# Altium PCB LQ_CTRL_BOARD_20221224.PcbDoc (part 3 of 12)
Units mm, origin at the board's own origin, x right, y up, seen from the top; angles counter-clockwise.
Board outline 260 x 142 mm, 6 copper layers (Top Layer, Mid-Layer 1, Mid-Layer 2, Mid-Layer 3, Mid-Layer 4, Bottom Layer); 1105 components, 1039 nets, 3898 pads, 1277 vias.
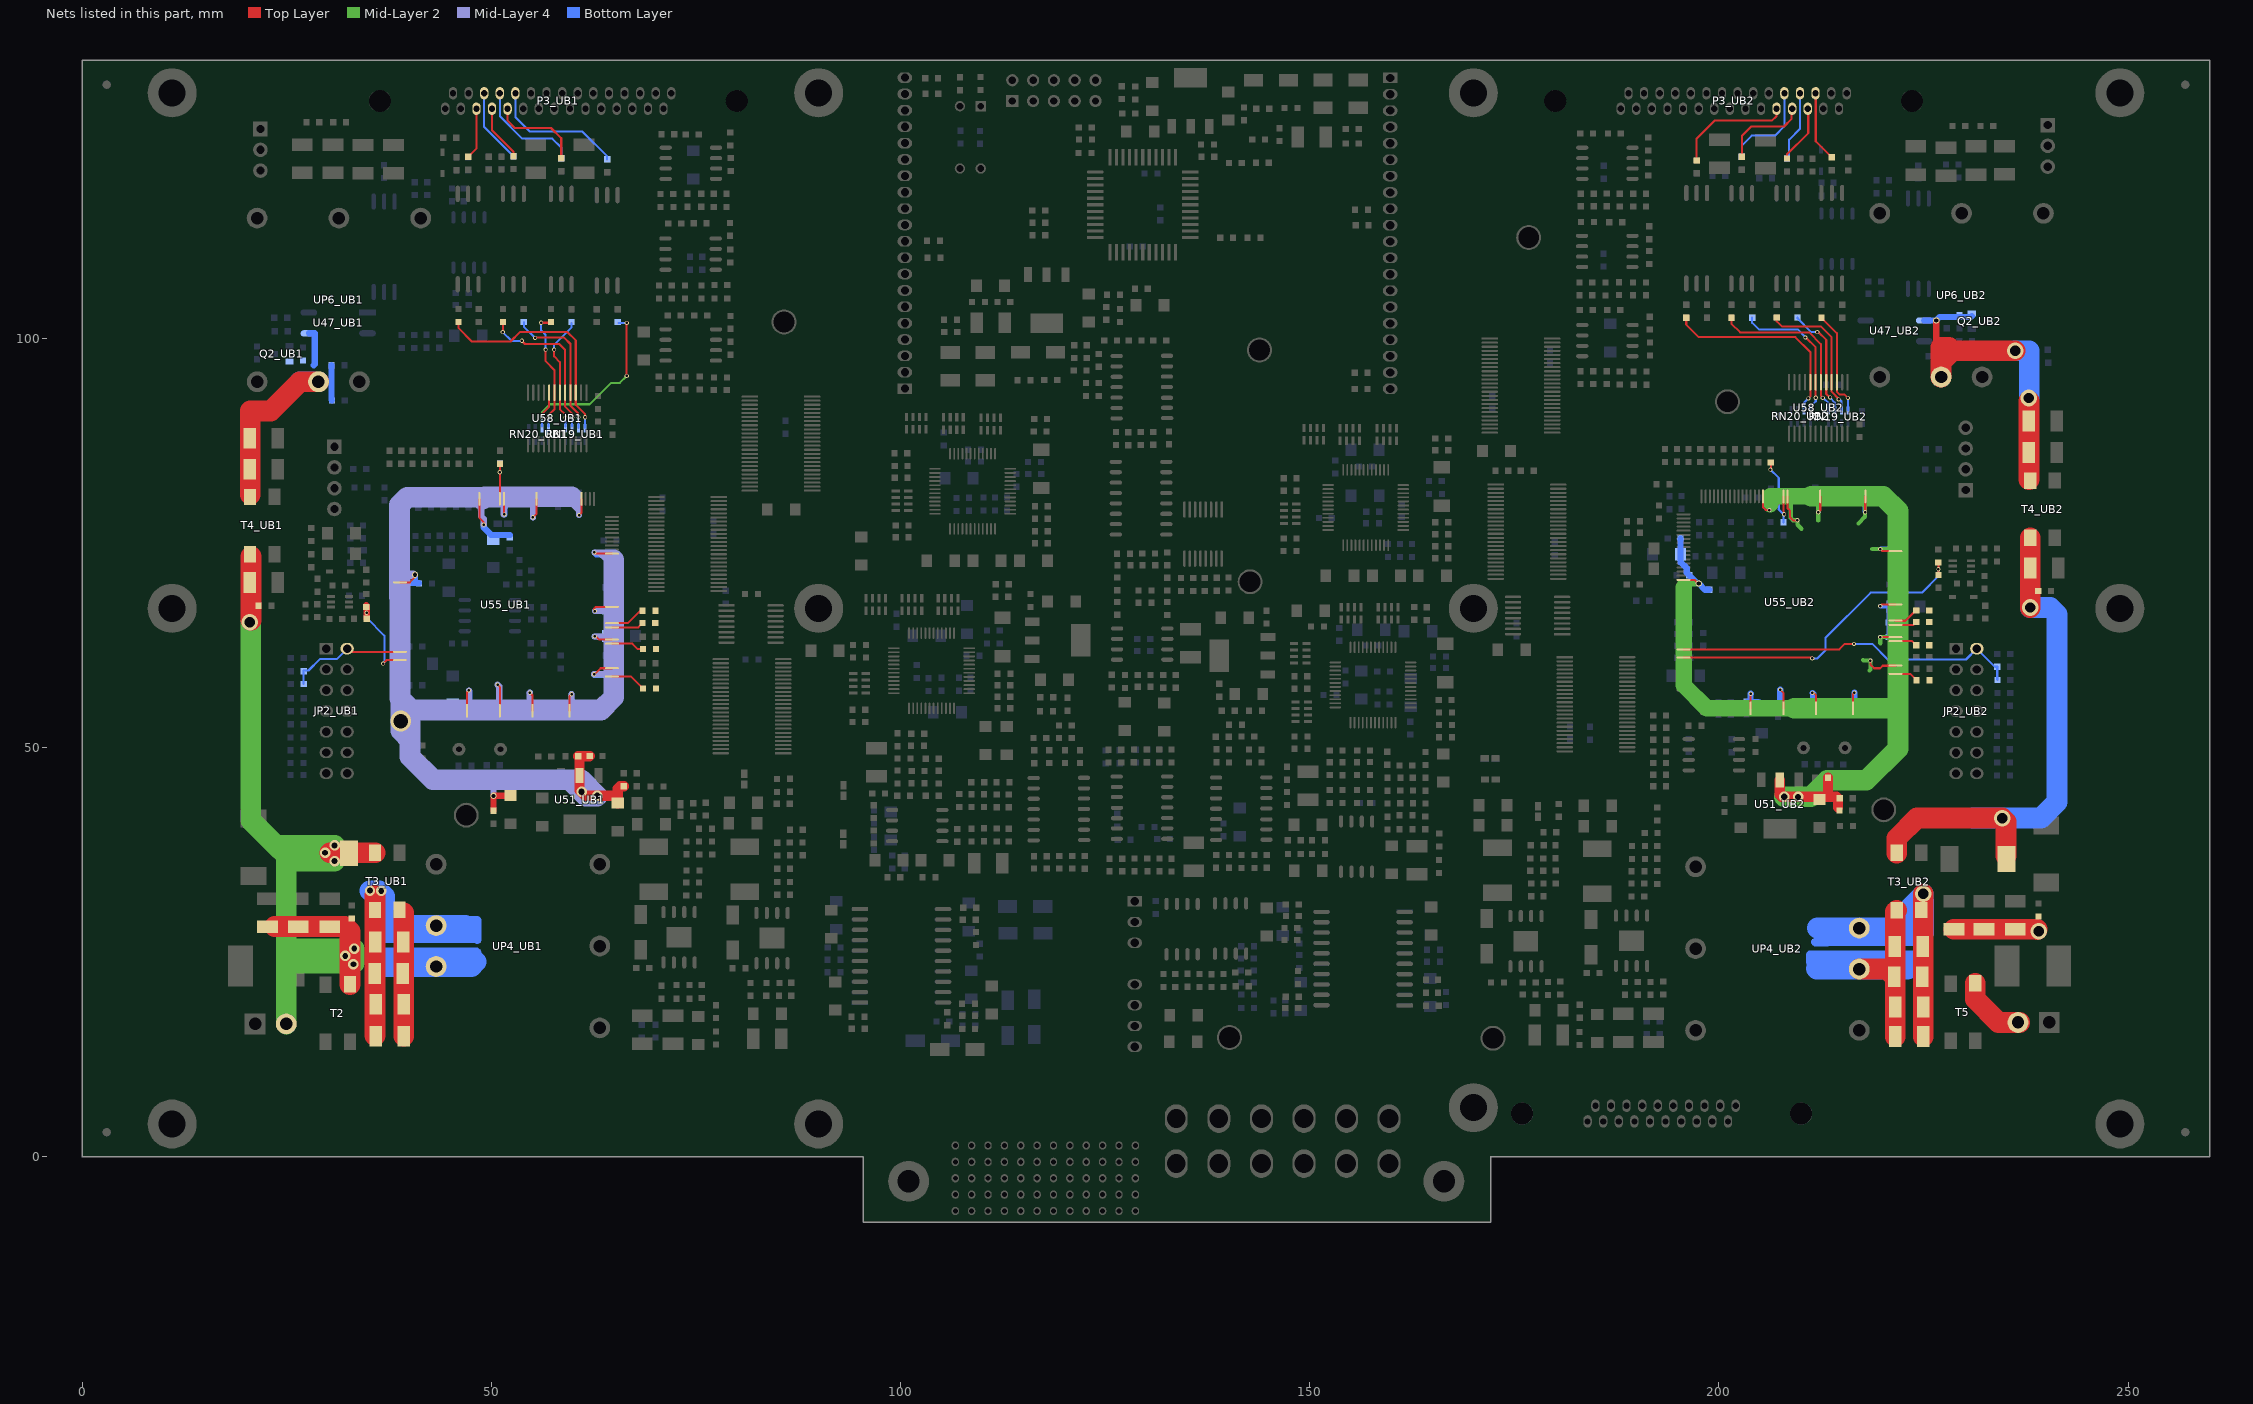
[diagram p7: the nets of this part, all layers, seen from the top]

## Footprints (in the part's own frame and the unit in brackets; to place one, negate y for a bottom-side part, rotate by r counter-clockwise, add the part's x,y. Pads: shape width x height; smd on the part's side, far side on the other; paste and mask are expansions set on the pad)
HDR2X5 [mm] "Connector; Header; 5x2 Position"
  rect 1.5x1.5 hole 0.9: 1(0,0)
  round 1.5 hole 0.9: 2(0,2.54) 3(2.54,0) 4(2.54,2.54) 5(5.08,0) 6(5.08,2.54) 7(7.62,0) 8(7.62,2.54) 9(10.16,0) 10(10.16,2.54)
  silkscreen extent -1.27,-1.27 11.43,3.81
WP_0603_LED [mil]
  rect 30x30 smd: 1(0,0) 2(62,0)
  silkscreen extent -53,-23 95,23
WP_0603C [mil]
  rect 30x30 smd: 1(0,0) 2(62,0)
  silkscreen extent -24,-23 86,23
WP_0603R [mil]
  rect 30x30 smd: 1(0,0) 2(62,0)
  silkscreen extent -23,-23 84,23
WP_1206CC [mil]
  rect 52.13x60 smd: 1(0,0) 2(135,0)
  silkscreen extent -36,-43 171,42
WP_1210CC [mil]
  rect 60x100 smd: 1(0,0) 2(135,0)
  silkscreen extent -44,-63 179,63
WP_2420 [mil]
  rect 120x196.85 smd: 1(0,0) 2(248,0)
  silkscreen extent -72,-109 319,108
WP_5032 [mil]
  rect 60x78.74 smd: 1(0,0) 2(185,0)
  silkscreen extent -46,-60 232,60
WP_ACM7060 [mm]
  rect 2x1.5 smd: 1(0,0.051) 2(7,0.051) 3(0.025,-2.949) 4(7,-2.949)
  silkscreen extent -0.99,-4.42 8,1.52
WP_CRM222-020 [mil]
  oval 40x60 hole 30: 1(0,0) 2(-75,0) 3(-150,0) 4(-225,0) 5(-300,0) 6(-375,0) 7(-450,0) 8(-525,0) 9(-600,0) 10(-675,0) 11(-37.5,75) 12(-112.5,75) 13(-187.5,75) 14(-262.5,75) 15(-337.5,75) 16(-412.5,75) 17(-487.5,75) 18(-562.5,75) 19(-637.5,75) 20(-712.5,75)
  round 106.3 hole 106.3: ""(-1027.51,37.5) ""(315.01,37.5)
  silkscreen extent -1112,-62 400,138
WP_CRM222-030 [mil]
  oval 40x60 hole 30: 1(0,0) 2(-75,0) 3(-150,0) 4(-225,0) 5(-300,0) 6(-375,0) 7(-450,0) 8(-525,0) 9(-600,0) 10(-675,0) 11(-750,0) 12(-825,0) 13(-900,0) 14(-975,0) 15(-1050,0) 16(-37.48,75) 17(-112.48,75) 18(-187.48,75) 19(-262.48,75) 20(-337.48,75) 21(-412.48,75) 22(-487.48,75) 23(-562.48,75) 24(-637.48,75) 25(-712.48,75) 26(-787.48,75) 27(-862.48,75) 28(-937.48,75) 29(-1012.48,75) 30(-1087.48,75)
  round 106.3 hole 106.3: ""(-1402.48,37.5) ""(314.04,37.5)
  silkscreen extent -1489,-63 401,138
WP_DIP4 [mil]
  rect 50x50 hole 32: 1(1,0)
  round 50 hole 32: 2(1,-100) 3(301,-100) 4(301,0)
  silkscreen extent 51,-150 251,50
WP_HEADER20S [mm]
  rect 1.3x1.8 hole 1: 1(0,0)
  oval 1.3x1.8 hole 1: 2(2,0) 3(4,0) 4(6,0) 5(8,0) 6(10,0) 7(12,0) 8(14,0) 9(16,0) 10(18,0) 11(20,0) 12(22,0) 13(24,0) 14(26,0) 15(28,0) 16(30,0) 17(32,0) 18(34,0) 19(36,0) 20(38,0)
  silkscreen extent -2,-1.46 40,1.47
WP_IDC14 [mil]
  rect 55x65 hole 40: 1(0,0)
  oval 55x65 hole 40: 2(0,100) 3(100,0) 4(100,100) 5(200,0) 6(200,100) 7(300,0) 8(300,100) 9(400,0) 10(400,100) 11(500,0) 12(500,100) 13(600,0) 14(600,100)
  silkscreen extent -65,-66 668,164
WP_JS2 [mil]
  rect 40x30 smd: 1(5,0) 2(56,0)
  silkscreen extent -23,-23 84,23
WP_LBS6*6 [mm]
  rect 2x3.5 smd: 1(0,0) 2(5.5,0)
  silkscreen extent -1.19,-3 6.71,3
WP_LRM5-A60H12RB-T2 [mm]
  oval 2.8x3.5 hole 2.3: 1(32.7,7.66) 2(37.9,7.66) 3(43.1,7.66) 4(48.3,7.66) 5(53.5,7.66) 6(58.7,7.66) 7(32.7,2.16) 8(37.9,2.16) 9(43.1,2.16) 10(48.3,2.16) 11(53.5,2.16) 12(58.7,2.16)
  oval 0.9x1.016 hole 0.6: A1(5.7,-3.63) A2(7.7,-3.63) A3(9.7,-3.63) A4(11.7,-3.63) A5(13.7,-3.63) A6(15.7,-3.63) A7(17.7,-3.63) A8(19.7,-3.63) A9(21.7,-3.63) A10(23.7,-3.63) A11(25.7,-3.63) A12(27.7,-3.63) B1(5.7,-1.63) B2(7.7,-1.63) B3(9.7,-1.63) B4(11.7,-1.63) B5(13.7,-1.63) B6(15.7,-1.63) B7(17.7,-1.63) B8(19.7,-1.63) B9(21.7,-1.63) B10(23.7,-1.63) B11(25.7,-1.63) B12(27.7,-1.63) C1(5.7,0.37) C2(7.7,0.37) C3(9.7,0.37) C4(11.7,0.37) C5(13.7,0.37) C6(15.7,0.37) C7(17.7,0.37) C8(19.7,0.37) C9(21.7,0.37) C10(23.7,0.37) C11(25.7,0.37) C12(27.7,0.37) D1(5.7,2.37) D2(7.7,2.37) D3(9.7,2.37) D4(11.7,2.37) D5(13.7,2.37) D6(15.7,2.37) D7(17.7,2.37) D8(19.7,2.37) D9(21.7,2.37) D10(23.7,2.37) D11(25.7,2.37) D12(27.7,2.37) E1(5.7,4.37) E2(7.7,4.37) E3(9.7,4.37) E4(11.7,4.37) E5(13.7,4.37) E6(15.7,4.37) E7(17.7,4.37) E8(19.7,4.37) E9(21.7,4.37) E10(23.7,4.37) E11(25.7,4.37) E12(27.7,4.37)
  round 5 hole 2.7: ""(0,0) ""(65.4,0)
  silkscreen extent -3.68,-20 69.12,11.43
WP_LSIP2 [mil]
  rect 100x100 hole 60: 1(0,0)
  round 100 hole 60: 2(150,0)
  silkscreen extent -106,-136 252,142
WP_PQFP176 [mm]
  rect 1.7x0.245 smd: 1(0,0)
  oval 1.7x0.245 smd: 2(0,-0.5) 3(0,-1) 4(0,-1.5) 5(0,-2) 6(0,-2.5) 7(0,-3) 8(0,-3.5) 9(0,-4) 10(0,-4.5) 11(0,-5) 12(0,-5.5) 13(0,-6) 14(0,-6.5) 15(0,-7) 16(0,-7.5) 17(0,-8) 18(0,-8.5) 19(0,-9) 20(0,-9.5) 21(0,-10) 22(0,-10.5) 23(0,-11) 24(0,-11.5) 25(0,-12) 26(0,-12.5) 27(0,-13) 28(0,-13.5) 29(0,-14) 30(0,-14.5) 31(0,-15) 32(0,-15.5) 33(0,-16) 34(0,-16.5) 35(0,-17) 36(0,-17.5) 37(0,-18) 38(0,-18.5) 39(0,-19) 40(0,-19.5) 41(0,-20) 42(0,-20.5) 43(0,-21) 44(0,-21.5) 89(25.9,-21.5) 90(25.9,-21) 91(25.9,-20.5) 92(25.9,-20) 93(25.9,-19.5) 94(25.9,-19) 95(25.9,-18.5) 96(25.9,-18) 97(25.9,-17.5) 98(25.9,-17) 99(25.9,-16.5) 100(25.9,-16) 101(25.9,-15.5) 102(25.9,-15) 103(25.9,-14.5) 104(25.9,-14) 105(25.9,-13.5) 106(25.9,-13) 107(25.9,-12.5) 108(25.9,-12) 109(25.9,-11.5) 110(25.9,-11) 111(25.9,-10.5) 112(25.9,-10) 113(25.9,-9.5) 114(25.9,-9) 115(25.9,-8.5) 116(25.9,-8) 117(25.9,-7.5) 118(25.9,-7) 119(25.9,-6.5) 120(25.9,-6) 121(25.9,-5.5) 122(25.9,-5) 123(25.9,-4.5) 124(25.9,-4) 125(25.9,-3.5) 126(25.9,-3) 127(25.9,-2.5) 128(25.9,-2) 129(25.9,-1.5) 130(25.9,-1) 131(25.9,-0.5) 132(25.9,0)
  oval 0.245x1.7 smd: 45(2.2,-23.7) 46(2.7,-23.7) 47(3.2,-23.7) 48(3.7,-23.7) 49(4.2,-23.7) 50(4.7,-23.7) 51(5.2,-23.7) 52(5.7,-23.7) 53(6.2,-23.7) 54(6.7,-23.7) 55(7.2,-23.7) 56(7.7,-23.7) 57(8.2,-23.7) 58(8.7,-23.7) 59(9.2,-23.7) 60(9.7,-23.7) 61(10.2,-23.7) 62(10.7,-23.7) 63(11.2,-23.7) 64(11.7,-23.7) 65(12.2,-23.7) 66(12.7,-23.7) 67(13.2,-23.7) 68(13.7,-23.7) 69(14.2,-23.7) 70(14.7,-23.7) 71(15.2,-23.7) 72(15.7,-23.7) 73(16.2,-23.7) 74(16.7,-23.7) 75(17.2,-23.7) 76(17.7,-23.7) 77(18.2,-23.7) 78(18.7,-23.7) 79(19.2,-23.7) 80(19.7,-23.7) 81(20.2,-23.7) 82(20.7,-23.7) 83(21.2,-23.7) 84(21.7,-23.7) 85(22.2,-23.7) 86(22.7,-23.7) 87(23.2,-23.7) 88(23.7,-23.7) 133(23.7,2.2) 134(23.2,2.2) 135(22.7,2.2) 136(22.2,2.2) 137(21.7,2.2) 138(21.2,2.2) 139(20.7,2.2) 140(20.2,2.2) 141(19.7,2.2) 142(19.2,2.2) 143(18.7,2.2) 144(18.2,2.2) 145(17.7,2.2) 146(17.2,2.2) 147(16.7,2.2) 148(16.2,2.2) 149(15.7,2.2) 150(15.2,2.2) 151(14.7,2.2) 152(14.2,2.2) 153(13.7,2.2) 154(13.2,2.2) 155(12.7,2.2) 156(12.2,2.2) 157(11.7,2.2) 158(11.2,2.2) 159(10.7,2.2) 160(10.2,2.2) 161(9.7,2.2) 162(9.2,2.2) 163(8.7,2.2) 164(8.2,2.2) 165(7.7,2.2) 166(7.2,2.2) 167(6.7,2.2) 168(6.2,2.2) 169(5.7,2.2) 170(5.2,2.2) 171(4.7,2.2) 172(4.2,2.2) 173(3.7,2.2) 174(3.2,2.2) 175(2.7,2.2) 176(2.2,2.2)
  silkscreen extent -1.24,-24.99 27.18,3.45
WP_RP4 [mil]
  rect 15x40 smd: 1(46.75,-84) 2(46.75,-24) 3(78.25,-84) 4(78.25,-24) 5(109.75,-84) 6(109.75,-24) 7(141.25,-84) 8(141.25,-24)
  silkscreen extent 10,-104 168,-4
WP_SIP3 [mil]
  rect 70x70 hole 40: 1(0,0)
  round 70 hole 40: 2(100,0) 3(200,0)
  silkscreen extent -50,-120 280,100
WP_SIP4 [mil]
  rect 70x70 hole 40: 1(0,0)
  round 70 hole 40: 2(100,0) 3(200,0) 4(300,0)
  silkscreen extent -50,-120 350,100
WP_SMA_DO214AC [mm]
  rect 2.35x1.55 smd: 1(0,0) 2(4.3,0)
  silkscreen extent -0.65,-1.5 5.73,1.5, body extent -0.45,-1.3 4.75,1.3, height 2.64
WP_SMC_DO214AB [mm]
  rect 2.2x3.15 smd: 1(0,0) 2(7,0)
  silkscreen extent -0.55,-3.15 8.33,3.15, body extent -0.45,-2.95 7.45,2.95, height 2.67
WP_SOD-323 [mm]
  rect 0.9x0.5 smd: 1(-0.025,0.025) 2(2.575,0.025)
  silkscreen extent 0.37,-0.65 2.76,0.7, body extent -0.08,-0.6 2.62,0.65, height 1.1
WP_SOIC6L [mm]
  oval 2x0.5 smd: 1(0,0) 2(0,-1.27) 3(0,-2.54) 4(11.049,-2.54) 5(11.049,-1.27) 6(11.049,0)
  silkscreen extent 1.45,-3.71 9.53,1.04
WP_SOIC8 [mm]
  oval 1.5x0.5 smd: 1(-1.473,-0.66) 2(-1.473,-1.93) 3(-1.473,-3.2) 4(-1.473,-4.47) 5(4.674,-4.47) 6(4.674,-3.2) 7(4.674,-1.93) 8(4.674,-0.66)
  silkscreen extent -0.03,-5.08 3.23,0.03
WP_SOIC8P [mil]
  oval 59.06x19.68 smd: 1(-2,1) 2(-2,-49) 3(-2,-99) 4(-2,-149) 5(240,-149) 6(240,-99) 7(240,-49) 8(240,1)
  rect 100x120 smd: 9(119,-73)
  silkscreen extent 55,-173 183,28
WP_SOIC14 [mm]
  oval 1.5x0.5 smd: 1(-1.219,-0.889) 2(-1.219,-2.159) 3(-1.219,-3.429) 4(-1.219,-4.699) 5(-1.219,-5.969) 6(-1.219,-7.239) 7(-1.219,-8.509) 8(4.953,-8.484) 9(4.928,-7.214) 10(4.928,-5.994) 11(4.928,-4.674) 12(4.928,-3.404) 13(4.928,-2.159) 14(4.928,-0.864)
  silkscreen extent 0.03,-9.12 3.68,0.05
WP_SOIC16 [mm]
  oval 1.5x0.5 smd: 1(-1.067,-0.94) 2(-1.067,-2.21) 3(-1.067,-3.48) 4(-1.067,-4.75) 5(-1.067,-6.02) 6(-1.067,-7.29) 7(-1.067,-8.56) 8(-1.067,-9.83) 9(5.105,-9.83) 10(5.105,-8.56) 11(5.105,-7.29) 12(5.105,-6.02) 13(5.105,-4.75) 14(5.105,-3.48) 15(5.105,-2.21) 16(5.105,-0.94)
  silkscreen extent 0.18,-10.54 3.84,0
WP_SOIC20L [mil]
  rect 78.74x20 smd: 1(-2,1)
  oval 78.74x20 smd: 2(-2,-49) 3(-2,-99) 4(-2,-149) 5(-2,-199) 6(-2,-249) 7(-2,-299) 8(-2,-349) 9(-2,-399) 10(-2,-449) 11(398,-449) 12(398,-399) 13(398,-350) 14(398,-300) 15(398,-250) 16(398,-200) 17(398,-150) 18(398,-100) 19(398,-50) 20(398,0)
  silkscreen extent 56,-483 341,24
WP_SOP4 [mil]
  rect 80x30 smd: 1(11,1)
  oval 80x30 smd: 3(11,-99) 4(293,-99) 6(293,1)
  silkscreen extent 63,-140 241,51
WP_SOT23B [mil]
  rect 30x40 smd: 1(0,0) 2(74,0) 3(37,76)
  silkscreen extent -19,-24 93,100
WP_SOT223 [mm]
  rect 1x1.8 smd: 1(0.864,-4.47) 2(3.175,-4.47) 3(5.436,-4.496)
  rect 4x2.4 smd: 4(3.15,1.473)
  silkscreen extent 0,-3.35 6.27,0
WP_SOT363 [mil]
  rect 40x14 smd: 1(0,0) 2(0,-25.59) 3(0,-51.18) 4(87,-51.18) 5(87,-25.59) 6(87,0)
  silkscreen extent 26,-67 60,14
WP_TQ48 [mm]
  rect 1.4x0.22 smd: 1(0.963,-2.863)
  oval 1.4x0.22 smd: 2(0.963,-3.363) 3(0.963,-3.863) 4(0.963,-4.363) 5(0.963,-4.863) 6(0.963,-5.363) 7(0.963,-5.863) 8(0.963,-6.363) 9(0.963,-6.863) 10(0.963,-7.363) 11(0.963,-7.863) 12(0.963,-8.363) 25(10.163,-8.363) 26(10.163,-7.863) 27(10.163,-7.363) 28(10.163,-6.863) 29(10.163,-6.363) 30(10.163,-5.863) 31(10.163,-5.363) 32(10.163,-4.863) 33(10.163,-4.363) 34(10.163,-3.863) 35(10.163,-3.363) 36(10.163,-2.863)
  oval 0.22x1.4 smd: 13(2.813,-10.213) 14(3.313,-10.213) 15(3.813,-10.213) 16(4.313,-10.213) 17(4.813,-10.213) 18(5.313,-10.213) 19(5.813,-10.213) 20(6.313,-10.213) 21(6.813,-10.213) 22(7.313,-10.213) 23(7.813,-10.213) 24(8.313,-10.213) 37(8.313,-1.013) 38(7.813,-1.013) 39(7.313,-1.013) 40(6.813,-1.013) 41(6.313,-1.013) 42(5.813,-1.013) 43(5.313,-1.013) 44(4.813,-1.013) 45(4.313,-1.013) 46(3.813,-1.013) 47(3.313,-1.013) 48(2.813,-1.013)
  silkscreen extent -0.14,-11.31 11.26,0.09
WP_TQFP44 [mm]
  oval 2x0.38 smd: 1(0,0)
  rect 2x0.38 smd: 2(0,-0.8) 3(0,-1.6) 4(0,-2.4) 5(0,-3.2) 6(0,-4) 7(0,-4.8) 8(0,-5.6) 9(0,-6.4) 10(0,-7.2) 11(0,-8) 23(11.6,-8) 24(11.6,-7.2) 25(11.6,-6.4) 26(11.6,-5.6) 27(11.6,-4.8) 28(11.6,-4) 29(11.6,-3.2) 30(11.6,-2.4) 31(11.6,-1.6) 32(11.6,-0.8) 33(11.6,0)
  rect 0.38x2 smd: 12(1.8,-9.8) 13(2.6,-9.8) 14(3.4,-9.8) 15(4.2,-9.8) 16(5,-9.8) 17(5.8,-9.8) 18(6.6,-9.8) 19(7.4,-9.8) 20(8.2,-9.8) 21(9,-9.8) 22(9.8,-9.8) 34(9.8,1.8) 35(9,1.8) 36(8.2,1.8) 37(7.4,1.8) 38(6.6,1.8) 39(5.8,1.8) 40(5,1.8) 41(4.2,1.8) 42(3.4,1.8) 43(2.6,1.8) 44(1.8,1.8)
  silkscreen extent 1.54,-8.27 10.07,0.26
WP_TSSOP16 [mm]
  rect 2x0.305 smd: 1(0,0)
  oval 2x0.305 smd: 2(0,-0.65) 3(0,-1.3) 4(0,-1.95) 5(0,-2.6) 6(0,-3.25) 7(0,-3.9) 8(0,-4.55) 9(6,-4.55) 10(6,-3.9) 11(6,-3.25) 12(6,-2.6) 13(6,-1.95) 14(6,-1.3) 15(6,-0.65) 16(6,0)
  silkscreen extent 1.84,-4.88 4.17,0.33
WP_TSSOP24 [mm]
  rect 2x0.254 smd: 1(0,0)
  oval 2x0.254 smd: 2(0,-0.65) 3(0,-1.3) 4(0,-1.95) 5(0,-2.6) 6(0,-3.25) 7(0,-3.9) 8(0,-4.55) 9(0,-5.2) 10(0,-5.85) 11(0,-6.5) 12(0,-7.15) 13(6.3,-7.15) 14(6.3,-6.5) 15(6.3,-5.85) 16(6.3,-5.2) 17(6.3,-4.55) 18(6.3,-3.9) 19(6.3,-3.25) 20(6.3,-2.6) 21(6.3,-1.95) 22(6.3,-1.3) 23(6.3,-0.65) 24(6.3,0)
  silkscreen extent 1.84,-7.48 4.46,0.33
WP_TSSOP48 [mil]
  rect 80x10 smd: 1(0,0)
  oval 80x10 smd: 2(0,-19.69) 3(0,-39.37) 4(0,-59.06) 5(0,-78.74) 6(0,-98.42) 7(0,-118.11) 8(0,-137.79) 9(0,-157.48) 10(0,-177.17) 11(0,-196.85) 12(0,-216.53) 13(0,-236.22) 14(0,-255.9) 15(0,-275.59) 16(0,-295.28) 17(0,-314.96) 18(0,-334.65) 19(0,-354.33) 20(0,-374.01) 21(0,-393.7) 22(0,-413.38) 23(0,-433.07) 24(0,-452.76) 25(300,-452.76) 26(300,-433.07) 27(300,-413.38) 28(300,-393.7) 29(300,-374.01) 30(300,-354.33) 31(300,-334.65) 32(300,-314.96) 33(300,-295.28) 34(300,-275.59) 35(300,-255.9) 36(300,-236.22) 37(300,-216.53) 38(300,-196.85) 39(300,-177.17) 40(300,-157.48) 41(300,-137.79) 42(300,-118.11) 43(300,-98.42) 44(300,-78.74) 45(300,-59.06) 46(300,-39.37) 47(300,-19.69) 48(300,0)
  silkscreen extent 75,-474 225,22
WP_WRB_CKS [mil]
  rect 50x70 hole 40: 1(0,0)
  oval 50x70 hole 40: 2(100,0) 3(200,0) 5(400,0) 6(500,0) 7(600,0) 8(700,0)
  silkscreen extent -100,-300 800,100
WP_XTAL [mil]
  round 62 hole 28: 1(1,0) 2(201,0)
  silkscreen extent -99,-60 301,60
WP_YMD [mil]
  round 100 hole 60: 1(-1,1) 2(-1,-195.85) 3(786.4,-491.13) 4(786.4,-97.43) 5(786.4,296.28) 6(-1,296)
  silkscreen extent -100,-602 899,395

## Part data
C1_UB1 C1_UB2 C2_UB1 C2_UB2 C230_UB1 C230_UB2 C231_UB1 C231_UB2 C232_UB1 C232_UB2 C273_UB1 C273_UB2 C274_UB1 C274_UB2 C275_UB1 C275_UB2 C296_UB1 C296_UB2 C297_UB1 C297_UB2 C298_UB1 C298_UB2 C331_UB1 C331_UB2 C332_UB1 C332_UB2 C333_UB1 C333_UB2 C334_UB1 C334_UB2 C335_UB1 C335_UB2 C336_UB1 C336_UB2 C337_UB1 C337_UB2 C338_UB1 C338_UB2 C339_UB1 C339_UB2 C340_UB1 C340_UB2 C341_UB1 C341_UB2 C342_UB1 C342_UB2 C343_UB1 C343_UB2 C344_UB1 C344_UB2 C345_UB1 C345_UB2 C347_UB1 C347_UB2 C348_UB1 C348_UB2 C349_UB1 C349_UB2 C350_UB1 C350_UB2 C351_UB1 C351_UB2 C352_UB1 C352_UB2 C353_UB1 C353_UB2 C354_UB1 C354_UB2 C355_UB1 C355_UB2 C360_UB1 C360_UB2 C361_UB1 C361_UB2 C366_UB1 C366_UB2 C371_UB1 C371_UB2 C372_UB1 C372_UB2 C375_UB1 C375_UB2 C376_UB1 C376_UB2: library part Cap, "Capacitor"
C3 C6 C12_UB1 C12_UB2 C16_UB1 C16_UB2 C17_UB1 C17_UB2 C217_UB1 C217_UB2 C218_UB1 C218_UB2 C219_UB1 C219_UB2 C220_UB1 C220_UB2 C221_UB1 C221_UB2 C222_UB1 C222_UB2 C223_UB1 C223_UB2 C228_UB1 C228_UB2 C233_UB1 C233_UB2 C256_UB1 C256_UB2 C257_UB1 C257_UB2 C263_UB1 C263_UB2 C265_UB1 C265_UB2 C267_UB1 C267_UB2 C270_UB1 C270_UB2 C271_UB1 C271_UB2 C276_UB1 C276_UB2 C278_UB1 C278_UB2 C279_UB1 C279_UB2 C283_UB1 C283_UB2 C288_UB1 C288_UB2 C289_UB1 C289_UB2 C294_UB1 C294_UB2 C309_UB1 C309_UB2 C367_UB1 C367_UB2 C369_UB1 C369_UB2 C379_UB1 C379_UB2 C383_UB1 C383_UB2 C424 C428 C429: library part Cap2, "Capacitor"
C4 C11_UB1 C11_UB2 C212_UB1 C212_UB2 C213_UB1 C213_UB2 C214_UB1 C214_UB2 C215_UB1 C215_UB2 C216_UB1 C216_UB2 C224_UB1 C224_UB2 C227_UB1 C227_UB2 C236_UB1 C236_UB2 C241_UB1 C241_UB2 C250_UB1 C250_UB2 C251_UB1 C251_UB2 C259_UB1 C259_UB2 C260_UB1 C260_UB2 C261_UB1 C261_UB2 C262_UB1 C262_UB2 C266_UB1 C266_UB2 C268_UB1 C268_UB2 C284_UB1 C284_UB2 C285_UB1 C285_UB2 C286_UB1 C286_UB2 C287_UB1 C287_UB2 C310_UB1 C310_UB2 C320_UB1 C320_UB2 C321_UB1 C321_UB2 C322_UB1 C322_UB2 C323_UB1 C323_UB2 C327_UB1 C327_UB2 C328_UB1 C328_UB2 C356_UB1 C356_UB2 C357_UB1 C357_UB2 C358_UB1 C358_UB2 C359_UB1 C359_UB2 C362_UB1 C362_UB2 C363_UB1 C363_UB2 C364_UB1 C364_UB2 C365_UB1 C365_UB2 C368_UB1 C368_UB2 C370_UB1 C370_UB2 C373_UB1 C373_UB2 C374_UB1 C374_UB2 C377_UB1 C377_UB2 C378_UB1 C378_UB2 C384_UB1 C384_UB2 C390_UB1 C390_UB2 C391_UB1 C391_UB2 C395_UB1 C395_UB2 C396_UB1 C396_UB2 C397_UB1 C397_UB2 C407_UB1 C407_UB2 C409_UB1 C409_UB2 C410_UB1 C410_UB2 C411_UB1 C411_UB2 C412_UB1 C412_UB2 C413_UB1 C413_UB2 C414_UB1 C414_UB2 C415_UB1 C415_UB2 C416_UB1 C416_UB2 C417_UB1 C417_UB2 C418_UB1 C418_UB2 C419_UB1 C419_UB2 C420_UB1 C420_UB2 C421_UB1 C421_UB2 C422_UB1 C422_UB2 C425 C426 C427 C430 C431 C434 C435 C438 C439 C440 C442 C443 C446 C447 C448: library part CAP, "Capacitor"
C5 C7 C8 C9 C13_UB1 C13_UB2 C14_UB1 C14_UB2 C15_UB1 C15_UB2 C225_UB1 C225_UB2 C234_UB1 C234_UB2 C235_UB1 C235_UB2 C237_UB1 C237_UB2 C238_UB1 C238_UB2 C248_UB1 C248_UB2 C252_UB1 C252_UB2 C258_UB1 C258_UB2 C264_UB1 C264_UB2 C269_UB1 C269_UB2 C272_UB1 C272_UB2 C277_UB1 C277_UB2 C280_UB1 C280_UB2 C281_UB1 C281_UB2 C282_UB1 C282_UB2 C290_UB1 C290_UB2 C293_UB1 C293_UB2 C295_UB1 C295_UB2 C299_UB1 C299_UB2 C300_UB1 C300_UB2 C301_UB1 C301_UB2 C302_UB1 C302_UB2 C303_UB1 C303_UB2 C304_UB1 C304_UB2 C305_UB1 C305_UB2 C306_UB1 C306_UB2 C307_UB1 C307_UB2 C308_UB1 C308_UB2 C315_UB1 C315_UB2 C316_UB1 C316_UB2 C317_UB1 C317_UB2 C318_UB1 C318_UB2 C319_UB1 C319_UB2 C324_UB1 C324_UB2 C325_UB1 C325_UB2 C326_UB1 C326_UB2 C329_UB1 C329_UB2 C330_UB1 C330_UB2 C346_UB1 C346_UB2 C385_UB1 C385_UB2 C386_UB1 C386_UB2 C387_UB1 C387_UB2 C388_UB1 C388_UB2 C408_UB1 C408_UB2 C441 C445 C449 C450 C451 C452 C453 C454: library part "Cap Semi", "Capacitor (Semiconductor SIM Model)"
C10_UB1 C242_UB1 C242_UB2 C380_UB1 C380_UB2 C389_UB1 C389_UB2 C392_UB1 C392_UB2 C398_UB1 C398_UB2 C399_UB1 C399_UB2 C400_UB1 C400_UB2 C401_UB1 C401_UB2 C403_UB1 C403_UB2 C404_UB1 C404_UB2 C444: library part CAP
C10_UB2: library part Cap
C254_UB1 C254_UB2 C255_UB1 C255_UB2 C291_UB1 C291_UB2 C292_UB1 C292_UB2 C381_UB1 C381_UB2 C382_UB1 C382_UB2 C402_UB1 C402_UB2: library part CAP1
C311_UB1 C311_UB2 C312_UB1 C312_UB2 C313_UB1 C313_UB2 C314_UB1 C314_UB2 C393_UB1 C393_UB2 C394_UB1 C394_UB2 C432 C433 C436 C437: library part ELECTRO1, "Electrolytic Capacitor"
C405_UB1 C405_UB2 C406_UB1 C406_UB2: library part 0805, "Capacitor"
D13_UB1 D13_UB2 D20_UB1 D20_UB2 D22_UB1 D22_UB2 D25 D26 D27 D28: library part "DIODE SCHOTTKY", "Schottky Diode"
D16_UB1 D16_UB2: library part Diode, "Default Diode"
D21_UB1 D21_UB2 D23_UB1 D23_UB2: library part LED0, "Typical INFRARED GaAs LED"
D24_UB1 D24_UB2: library part DIODE, "Diode"
DR2_UB1 DR2_UB2 DR3 DR4: library part TVS
DR5 DR6 DR7 DR8 DR9 DR10: library part TVS, "Resistor"
F1_UB1 F1_UB2: library part "Fuse 2", "Fuse"
JP2_UB1 JP2_UB2: library part "HEADER 7X2"
JP3: "Header, 5-Pin, Dual row"
L3_UB1 L3_UB2 L4_UB1 L4_UB2: library part Inductor, "Inductor"
LED1 LED2 LED3 LED4 LED16 LED17 LED18 LED19 LED20 LED21: library part LED2
LED5_UB1 LED5_UB2 LED9_UB1 LED9_UB2 LED10_UB1 LED10_UB2 LED11_UB1 LED11_UB2 LED12_UB1 LED12_UB2 LED13_UB1 LED13_UB2 LED14_UB1 LED14_UB2 LED15_UB1 LED15_UB2: library part LED2, "Typical RED, GREEN, YELLOW, AMBER GaAs LED"
P1_UB1 P1_UB2: "Header, 3-Pin"
P2_UB1 P2_UB2: "Header, 4-Pin"
P3_UB1 P3_UB2: "Header, 15-Pin, Dual row"
P4_UB1 P4_UB2: "Header, 20-Pin"
P7: "Header, 10-Pin, Dual row"
P9_UB1 P9_UB2: "Header, 2-Pin"
R1 R2 R3_UB1 R3_UB2 R4_UB1 R4_UB2 R5 R6 R7 R8 R9 R10 R11 R12 R13 R14 R17_UB1 R17_UB2 R18_UB1 R18_UB2 R19_UB1 R19_UB2 R20_UB1 R20_UB2 R21_UB1 R21_UB2 R22_UB1 R22_UB2 R24 R25 R28_UB1 R28_UB2 R29_UB1 R29_UB2 R30_UB1 R30_UB2 R31 R32 R33 R34 R35 R36 R37 R38 R39_UB1 R39_UB2 R40_UB1 R40_UB2 R41_UB1 R41_UB2 R187 R188 R192_UB1 R192_UB2 R195_UB1 R195_UB2 R196_UB1 R196_UB2 R197_UB1 R197_UB2 R198_UB1 R198_UB2 R200_UB1 R200_UB2 R203_UB1 R203_UB2 R205_UB1 R205_UB2 R207_UB1 R207_UB2 R209_UB1 R209_UB2 R210_UB1 R210_UB2 R212_UB1 R212_UB2 R213_UB1 R213_UB2 R214_UB1 R214_UB2 R216_UB1 R216_UB2 R217_UB1 R217_UB2 R219_UB1 R219_UB2 R220_UB1 R220_UB2 R221_UB1 R221_UB2 R222_UB1 R222_UB2 R223_UB1 R223_UB2 R224_UB1 R224_UB2 R225_UB1 R225_UB2 R228_UB1 R228_UB2 R230_UB1 R230_UB2 R231_UB1 R231_UB2 R235_UB1 R235_UB2 R237_UB1 R237_UB2 R244_UB1 R244_UB2 R248_UB1 R248_UB2 R251_UB1 R251_UB2 R252_UB1 R252_UB2 R255_UB1 R255_UB2 R261_UB1 R261_UB2 R265_UB1 R265_UB2 R266_UB1 R266_UB2 R267_UB1 R267_UB2 R270_UB1 R270_UB2 R271_UB1 R271_UB2 R272_UB1 R272_UB2 R275_UB1 R275_UB2 R278_UB1 R278_UB2 R279_UB1 R279_UB2 R280_UB1 R280_UB2 R281_UB1 R281_UB2 R282_UB1 R282_UB2 R283_UB1 R283_UB2 R284_UB1 R284_UB2 R285_UB1 R285_UB2 R286_UB1 R286_UB2 R287_UB1 R287_UB2 R288_UB1 R288_UB2 R289_UB1 R289_UB2 R290_UB1 R290_UB2 R291_UB1 R291_UB2 R292_UB1 R292_UB2 R293_UB1 R293_UB2 R297_UB1 R297_UB2 R298_UB1 R298_UB2 R299_UB1 R299_UB2 R300_UB1 R300_UB2 R301_UB1 R301_UB2 R302_UB1 R302_UB2 R303_UB1 R303_UB2 R304_UB1 R304_UB2 R305_UB1 R305_UB2 R306_UB1 R306_UB2 R307_UB1 R307_UB2 R308_UB1 R308_UB2 R309_UB1 R309_UB2 R310_UB1 R310_UB2 R311_UB1 R311_UB2 R312_UB1 R312_UB2 R313_UB1 R313_UB2 R314_UB1 R314_UB2 R315_UB1 R315_UB2 R316_UB1 R316_UB2 R317_UB1 R317_UB2 R318_UB1 R318_UB2 R319_UB1 R319_UB2 R320_UB1 R320_UB2 R321_UB1 R321_UB2 R322_UB1 R322_UB2 R323_UB1 R323_UB2 R324_UB1 R324_UB2 R326_UB1 R326_UB2 R327_UB1 R327_UB2 R329_UB1 R329_UB2 R330_UB1 R330_UB2 R332_UB1 R332_UB2 R333_UB1 R333_UB2 R334_UB1 R334_UB2 R335_UB1 R335_UB2 R336_UB1 R336_UB2 R337_UB1 R337_UB2 R338_UB1 R338_UB2 R339_UB1 R339_UB2 R340_UB1 R340_UB2 R341_UB1 R341_UB2 R342_UB1 R342_UB2 R343_UB1 R343_UB2 R344_UB1 R344_UB2 R346_UB1 R346_UB2 R347_UB1 R347_UB2 R348_UB1 R348_UB2 R349_UB1 R349_UB2 R350_UB1 R350_UB2 R352_UB1 R352_UB2 R358_UB1 R358_UB2 R361_UB1 R361_UB2 R362_UB1 R362_UB2 R363_UB1 R363_UB2 R364_UB1 R364_UB2 R367_UB1 R367_UB2 R368_UB1 R368_UB2 R369_UB1 R369_UB2 R370_UB1 R370_UB2 R372 R373 R374 R375 R376 R377 R378 R379 R380 R381 R382 R383 R384 R385 R386 R387 R388 R389 R390 R391 R392 R393 R394 R395 R396 R397 R398 R399 R400 R401 R403 R404 R405 R406 R407 R408 R409 R410 R411 R412 R413 R415 R416 R417 R418 R419 R420 R421 R422 R423 R424 R425 R426 R428 R429 R430 R432 R433 R434 R436: library part Res2, "Resistor"
R15_UB1 R15_UB2 R16_UB1 R16_UB2 R229_UB1 R229_UB2 R234_UB1 R234_UB2 R236_UB1 R236_UB2 R238_UB1 R238_UB2 R239_UB1 R239_UB2 R242_UB1 R242_UB2 R243_UB1 R243_UB2 R245_UB1 R245_UB2 R259_UB1 R259_UB2 R262_UB1 R262_UB2 R263_UB1 R263_UB2 R268_UB1 R268_UB2 R269_UB1 R269_UB2 R273_UB1 R273_UB2 R274_UB1 R274_UB2 R276_UB1 R276_UB2 R277_UB1 R277_UB2 R294_UB1 R294_UB2 R295_UB1 R295_UB2 R296_UB1 R296_UB2 R325_UB1 R325_UB2 R328_UB1 R328_UB2 R331_UB1 R331_UB2 R345_UB1 R345_UB2 R366_UB1 R366_UB2: library part RES
R23_UB1 R23_UB2 R26_UB1 R26_UB2 R27_UB1 R27_UB2 R194_UB1 R194_UB2 R215_UB1 R215_UB2 R218_UB1 R218_UB2 R226_UB1 R226_UB2 R227_UB1 R227_UB2 R232_UB1 R232_UB2 R233_UB1 R233_UB2 R240_UB1 R240_UB2 R241_UB1 R241_UB2 R246_UB1 R246_UB2 R247_UB1 R247_UB2 R249_UB1 R249_UB2 R250_UB1 R250_UB2 R253_UB1 R253_UB2 R254_UB1 R254_UB2 R256_UB1 R256_UB2 R257_UB1 R257_UB2 R258_UB1 R258_UB2 R260_UB1 R260_UB2 R264_UB1 R264_UB2 R431 R435: library part WP_RES
R353_UB1 R353_UB2 R355_UB1 R355_UB2 R356_UB1 R356_UB2 R359_UB1 R359_UB2: library part RES2
R365_UB1 R365_UB2 R371_UB1 R371_UB2: library part R
RN11_UB1 RN11_UB2 RN12_UB1 RN12_UB2 RN13_UB1 RN13_UB2 RN14_UB1 RN14_UB2 RN15_UB1 RN15_UB2 RN16_UB1 RN16_UB2 RN17_UB1 RN17_UB2 RN18_UB1 RN18_UB2 RN19_UB1 RN19_UB2 RN20_UB1 RN20_UB2: library part WP_RP4
S1: "DIP Switch, 2 Position, SPST"
T2 T3_UB1 T3_UB2 T4_UB1 T4_UB2 T5: library part Trans, "Transformer"
U1 U2 U35_UB1 U35_UB2: library part HCPL2531
U4_UB1 U4_UB2 U34_UB1 U34_UB2 U53_UB1 U53_UB2: library part SN74AVC16T245
U5: library part MULTI_HEADER
U32_UB1 U32_UB2 U48_UB1 U48_UB2 U49_UB1 U49_UB2 U50_UB1 U50_UB2 U67: library part LT1358, "Fast Settling Dual Operational Amplifier"
U42_UB1 U42_UB2 U54_UB1 U54_UB2: library part AD2S1210
U47_UB1 U47_UB2: library part TLP521-1
U51_UB1 U51_UB2 U56_UB1 U56_UB2 U65 U66: library part AS1117
U52 U52_UB1 U52_UB2: library part 74AVC4T245
U55_UB1 U55_UB2: library part "TMS320F28335-176 QFP"
U57_UB1 U57_UB2 U64 U69: library part TL084D, "JFET-Input Operational Amplifier"
U58_UB1 U58_UB2: library part SN74LVTH245A, "SN74LVC4245"
U59_UB1 U59_UB2: library part 74LVC2G14
U60_UB1 U60_UB2: library part X25040
U61_UB1 U61_UB2: library part ADM3053
U63: library part 74HC4052
U68: "No Description Available"
UP1: library part WRB1212S-3WR2
UP4_UB1 UP4_UB2 UP6_UB1 UP6_UB2: library part VRA2415D(X)-10WR2
X2_UB1 X2_UB2 Y3_UB1 Y3_UB2 Y4_UB1 Y4_UB2: library part CRYSTAL

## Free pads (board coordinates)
  round 3.048 hole 2.54: 0(85.776,102.006) 1(46.939,41.732) 2(140.208,14.58) 3(172.39,14.478) 4(142.723,70.256) 5(143.866,98.577) 6(176.759,112.319) 7(201.041,92.253) 8(220.142,42.393)
  round 1.016 smd: ""(3,3) ""(3,131) ""(257,3) ""(257,131)
  round 1.016 smd far side: ""(3,3) ""(3,131) ""(257,3) ""(257,131)
  round 6 hole 3.3: ""(11,4) ""(11,67) ""(11,130) ""(90,4) ""(90,67) ""(90,130) ""(170,6) ""(170,67) ""(170,130) ""(249,4) ""(249,67) ""(249,130)

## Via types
v1: diameter 0.508, hole 0.305, Top Layer to Bottom Layer, 845 vias
v2: diameter 0.762, hole 0.508, Top Layer to Bottom Layer, 317 vias
v3: diameter 1.27, hole 0.762, Top Layer to Bottom Layer, 77 vias
v4: diameter 2.032, hole 1.524, Top Layer to Bottom Layer, 15 vias
v5: diameter 2.032, hole 1.27, Top Layer to Bottom Layer, 11 vias
v6: diameter 1.27, hole 0.711, Top Layer to Bottom Layer, 8 vias
v7: diameter 2.54, hole 1.778, Top Layer to Bottom Layer, 3 vias
v8: diameter 1.524, hole 1.016, Top Layer to Bottom Layer, 1 vias

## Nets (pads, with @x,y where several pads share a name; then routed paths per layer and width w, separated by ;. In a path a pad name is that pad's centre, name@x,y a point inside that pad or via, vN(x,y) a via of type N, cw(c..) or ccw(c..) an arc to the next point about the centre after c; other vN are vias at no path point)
1PM1_UB1: R246_UB1.1 RN19_UB1.7 U58_UB1.3 | length 27.9
  Top Layer w0.254: R246_UB1.1@45.979,102.006 45.979,101.27 47.63,99.619 52.349,99.619 53.492,100.762 59.309,100.762 60.326,99.745 U58_UB1.3@60.326,93.37 60.326,91.871 61.468,90.729 v1(61.468,90.348)
  Bottom Layer w0.254: v1(61.468,90.348) 61.474,90.341 RN19_UB1.7@61.474,89.027
1PM1_UB2: R246_UB2.1 RN19_UB2.7 U58_UB2.3 | length 13
  Top Layer w0.254: R246_UB2.1@212.527,102.514 214.419,100.622 214.419,96.317 U58_UB2.3@214.419,94.64 214.419,93.479 214.782,93.116 215.367,93.116 v1(215.773,92.71)
  Bottom Layer w0.254: v1(215.773,92.71) 215.777,92.706 RN19_UB2.7@215.777,91.186
1PM2_UB1: R233_UB1.1 RN19_UB1.5 U58_UB1.4 | length 17.9
  Top Layer w0.254: v1(55.347,100.051) 55.376,100.08 58.899,100.08 59.676,99.303 U58_UB1.4@59.676,93.37 59.676,91.759 60.655,90.78 v1(60.655,90.348)
  Bottom Layer w0.254: R233_UB1.1@53.98,102.006 53.98,101.417 v1(55.347,100.051) ; v1(60.655,90.348) 60.674,90.329 RN19_UB1.5@60.674,89.027
1PM2_UB2: R233_UB2.1 RN19_UB2.5 U58_UB2.4 | length 17.6
  Top Layer w0.254: R233_UB2.1@207.061,102.54 207.061,102.083 207.721,101.422 212.496,101.422 213.769,100.149 U58_UB2.4@213.769,94.64 213.769,93.483 214.669,92.583 v1@214.681,92.583 ; v1(214.63,92.532) v1@214.732,92.532
  Bottom Layer w0.254: v1(214.63,92.532) 214.732,92.532 214.986,92.278 214.976,92.269 RN19_UB2.5@214.976,91.186
1PM3_UB1: R215_UB1.1 RN19_UB1.3 U58_UB1.5 | length 19.5
  Top Layer w0.254: v1@51.44,100.762 R215_UB1.1@51.44,102.006 ; v1(53.746,99.695) 54.127,99.314 58.293,99.314 59.026,98.581 U58_UB1.5@59.026,93.37 59.026,91.647 59.893,90.78 v1(59.893,90.348)
  Bottom Layer w0.254: v1(51.41,100.762) 52.476,99.695 v1(53.746,99.695) ; RN19_UB1.3@59.874,89.256 59.874,90.329 v1(59.893,90.348)
1PM3_UB2: R215_UB2.1 RN19_UB2.3 U58_UB2.5 | length 13.9
  Top Layer w0.254: v1(212.014,100.762) 212.166,100.762 213.119,99.809 U58_UB2.5@213.119,94.64 213.119,93.205 213.589,92.735 v1(213.589,92.786)
  Bottom Layer w0.254: R215_UB2.1@209.601,102.54 209.601,102.464 211.303,100.762 v1(212.014,100.762) ; v1(213.589,92.786) 213.589,92.735 214.176,92.148 RN19_UB2.3@214.176,91.186
1PM4_UB1: R249_UB1.1 RN19_UB1.1 U58_UB1.6 | length 14.1
  Top Layer w0.254: v1(57.683,98.628) 57.683,97.79 58.376,97.098 U58_UB1.6@58.376,93.37 58.376,91.357 59.08,90.653 v1(59.08,90.322)
  Bottom Layer w0.254: v1(57.683,98.628) 57.683,99.212 59.822,101.351 R249_UB1.1@59.822,101.879 ; RN19_UB1.1@59.074,89.256 59.074,90.316 v1(59.08,90.322)
1PM4_UB2: R249_UB2.1 RN19_UB2.1 U58_UB2.6 | length 21.4
  Top Layer w0.254: R249_UB2.1@201.529,102.514 201.529,101.798 202.59,100.736 211.023,100.736 212.469,99.29 212.469,96.317 U58_UB2.6@212.469,94.64 212.469,93.016 212.776,92.71 v1(212.7,92.71)
  Bottom Layer w0.254: v1(212.7,92.71) 212.776,92.71 213.36,92.126 213.376,92.142 RN19_UB2.1@213.376,91.186
1PM5_UB1: R232_UB1.1 RN20_UB1.7 U58_UB1.7 | length 14.8
  Top Layer w0.254: v1(56.083,101.905) 57.181,101.905 R232_UB1.1@57.282,102.006 ; v1(56.642,98.628) 56.642,97.206 57.726,96.122 U58_UB1.7@57.726,93.37 57.726,91.355 56.972,90.602 v1(56.972,90.348)
  Bottom Layer w0.254: v1(56.083,101.905) 56.083,100.965 56.642,100.406 v1(56.642,98.628) ; RN20_UB1.7@56.979,89.256 56.979,90.278 v1@56.998,90.297
1PM5_UB2: R232_UB2.1 RN20_UB2.7 U58_UB2.7 | length 17.7
  Top Layer w0.254: v1(210.566,100.101) 210.617,100.101 211.819,98.899 U58_UB2.7@211.819,94.64 211.819,92.752 v1(211.836,92.735)
  Bottom Layer w0.254: R232_UB2.1@204.069,102.514 204.069,101.899 204.876,101.092 209.626,101.092 210.617,100.101 v1(210.566,100.101) ; RN20_UB2.7@211.207,91.211 211.207,91.675 211.836,92.304 v1(211.836,92.735)
1PM6_UB1: R218_UB1.1 RN20_UB1.5 U58_UB1.8 | length 24.8
  Top Layer w0.254: v1(56.185,90.348) 56.185,90.729 57.076,91.62 U58_UB1.8@57.076,93.37 ; v1(66.548,95.402) v1(66.548,101.879)
  Mid-Layer 2 w0.254: v1(56.185,90.348) 56.185,90.957 57.175,91.948 62.027,91.948 64.643,94.564 65.71,94.564 v1(66.548,95.402)
  Bottom Layer w0.254: RN20_UB1.5@56.178,89.256 56.178,90.341 v1(56.185,90.348) ; R218_UB1.1@65.537,101.879 v1(66.548,101.879)
1PM6_UB2: R218_UB2.1 RN20_UB2.5 U58_UB2.8 | length 24.8
  Top Layer w0.254: R218_UB2.1@196.012,102.514 196.012,101.676 197.536,100.152 209.347,100.152 211.169,98.33 U58_UB2.8@211.169,94.64 211.169,92.882 v1(210.947,92.659)
  Bottom Layer w0.254: RN20_UB2.5@210.407,91.211 210.407,92.119 v1(210.947,92.659)
1PWM1_UB1: P3_UB1.3 R252_UB1.2 | length 6.3
  Top Layer w0.254: R252_UB1.2@47.174,122.174 48.184,123.183 P3_UB1.3@48.184,128.047
1PWM1_UB2: P3_UB2.3 R252_UB2.2 | length 8.7
  Top Layer w0.254: P3_UB2.3@211.836,129.952 211.836,124.084 R252_UB2.2@213.797,122.123 213.843,122.169 R252_UB2.2@213.843,122.149
1PWM2_UB1: P3_UB1.18 R235_UB1.2 | length 9.2
  Bottom Layer w0.254: P3_UB1.18@49.136,129.952 49.136,125.825 R235_UB1.2@52.71,122.25
1PWM2_UB2: P3_UB2.18 R235_UB2.2 | length 7.8
  Top Layer w0.254: R235_UB2.2@208.33,121.971 208.33,122.478 210.922,125.07 210.922,128.422 P3_UB2.18@210.744,128.6
1PWM3_UB1: P3_UB1.4 R224_UB1.2 | length 6.9
  Top Layer w0.254: P3_UB1.4@50.089,128.047 50.089,125.425 52.71,122.804 R224_UB1.2@52.71,122.25
1PWM3_UB2: P3_UB2.4 R224_UB2.2 | length 9.2
  Bottom Layer w0.254: P3_UB2.4@209.908,129.952 209.908,125.605 208.585,124.282 208.585,122.428 ; 208.585,122.428 208.33,122.173 R224_UB2.2@208.33,121.971 208.585,122.226 208.585,122.428
1PWM4_UB1: P3_UB1.19 R251_UB1.2 | length 13.2
  Bottom Layer w0.254: P3_UB1.19@51.041,129.952 51.041,127.166 53.797,124.409 57.455,124.409 58.552,123.312 R251_UB1.2@58.552,121.996
1PWM4_UB2: P3_UB2.19 R251_UB2.2 | length 11.3
  Top Layer w0.254: R251_UB2.2@202.799,122.174 202.799,124.719 203.962,125.882 207.95,125.882 208.89,126.822 P3_UB2.19@208.89,128.6
1PWM5_UB1: P3_UB1.5 R237_UB1.2 | length 11.4
  Top Layer w0.254: P3_UB1.5@51.994,128.047 51.994,126.594 52.883,125.705 57.302,125.705 58.552,124.455 R237_UB1.2@58.552,121.996
1PWM5_UB2: P3_UB2.5 R237_UB2.2 | length 12.2
  Bottom Layer w0.254: R237_UB2.2@202.799,122.174 202.799,123.551 204.013,124.765 206.858,124.765 208.001,125.908 P3_UB2.5@208.001,130.505
1PWM6_UB1: P3_UB1.20 R223_UB1.2 | length 16.5
  Bottom Layer w0.254: P3_UB1.20@52.946,129.952 52.946,127.039 54.712,125.273 61.138,125.273 64.16,122.25 R223_UB1.2@64.16,121.869
1PWM6_UB2: P3_UB2.20 R223_UB2.2 | length 14.5
  Top Layer w0.254: R223_UB2.2@197.287,121.742 197.287,124.415 199.466,126.594 206.477,126.594 207.051,127.168 P3_UB2.20@207.051,128.047
28GND_UB1: C212_UB1.2 C213_UB1.2 C215_UB1.2 C216_UB1.2 C217_UB1.2 C218_UB1.2 C219_UB1.2 C220_UB1.2 C230_UB1.1 C231_UB1.1 C232_UB1.1 T3_UB1.1 UP4_UB1.1 | length 52.2
  Top Layer w2.54: 35.763,31.928 35.789,31.902 T3_UB1.1@35.789,30.15 C219_UB1.2@35.789,14.814
  Bottom Layer w1.016: 36.982,28.55 36.678,28.245 C231_UB1.1@36.678,26.619 C232_UB1.1@38.176,26.619 C212_UB1.2@39.675,26.619 C213_UB1.2@41.25,26.619 47.6,26.619 ; 47.6,26.619 48.184,26.619 C216_UB1.2@48.285,26.518 48.285,28.88 47.447,28.88 46.812,28.245 47.6,27.457 47.6,26.619
  Bottom Layer w2.54: v6(35.179,32.512) 36.297,32.512 36.982,31.826 36.982,28.55 37.287,28.245 UP4_UB1.1@43.262,28.245 46.812,28.245
  other v6: 36.551,32.487
28GND_UB2: C212_UB2.2 C213_UB2.2 C215_UB2.2 C216_UB2.2 C217_UB2.2 C218_UB2.2 C219_UB2.2 C220_UB2.2 C230_UB2.1 C231_UB2.1 C232_UB2.1 T3_UB2.1 UP4_UB2.1 | length 48.2
  Top Layer w2.54: UP4_UB2.1@217.15,22.936 220.497,22.936 C219_UB2.2@221.437,21.996 ; C218_UB2.2@221.539,14.681 C217_UB2.2@221.539,18.313 221.539,29.921 T3_UB2.1@221.742,30.124
  Bottom Layer w1.016: 211.912,22.987 211.125,23.774 211.125,24.689 C215_UB2.2@214.782,24.689 C232_UB2.1@220.751,24.689 C230_UB2.1@223.85,24.689
  Bottom Layer w1.27: 223.063,22.936 223.85,23.724 ; 223.85,23.597 C230_UB2.1@223.85,24.562
  Bottom Layer w2.54: 211.912,22.987 211.963,22.936 UP4_UB2.1@217.15,22.936 223.063,22.936
28VA_UB1: C212_UB1.1 C213_UB1.1 C215_UB1.1 C216_UB1.1 C217_UB1.1 C218_UB1.1 C219_UB1.1 C220_UB1.1 C230_UB1.2 C231_UB1.2 C232_UB1.2 T3_UB1.3 UP4_UB1.2 | length 52.9
  Top Layer w2.54: C219_UB1.1@39.299,14.732 T3_UB1.3@39.299,29.82
  Bottom Layer w1.016: 37.033,23.216 36.271,23.978 36.271,25.044 C231_UB1.2@36.678,25.044 C232_UB1.2@38.176,25.044 C212_UB1.1@39.675,25.044 C213_UB1.1@41.25,25.044 48.184,25.044 C216_UB1.1@48.285,24.943
  Bottom Layer w2.54: 37.033,23.216 37.062,23.245 ; 46.812,23.216 46.783,23.245 ; 37.062,23.245 37.643,23.825 UP4_UB1.2@43.842,23.825 ; 37.062,23.245 UP4_UB1.2@43.262,23.245 ; UP4_UB1.2@43.262,23.245 46.783,23.245 ; UP4_UB1.2@43.262,23.245 UP4_UB1.2@43.842,23.825 ; UP4_UB1.2@43.842,23.825 48.158,23.825 47.578,23.245 46.783,23.245
28VA_UB2: C212_UB2.1 C213_UB2.1 C215_UB2.1 C216_UB2.1 C217_UB2.1 C218_UB2.1 C219_UB2.1 C220_UB2.1 C230_UB2.2 C231_UB2.2 C232_UB2.2 T3_UB2.3 UP4_UB2.2 | length 61.6
  Top Layer w2.54: C218_UB2.1@224.968,14.681 C217_UB2.1@224.968,18.313 v5(224.968,32.117)
  Bottom Layer w1.016: C212_UB2.1@213.258,26.187 211.811,26.187 C213_UB2.1@211.76,26.238 C231_UB2.2@222.326,26.238 224.815,26.238 225.781,27.203 225.781,31.305 v5(224.968,32.117)
  Bottom Layer w2.54: 212.039,27.936 UP4_UB2.2@217.15,27.936 220.853,27.936 ; v5(224.968,32.117) v5@224.968,32.051 ; 220.853,27.936 v5@224.968,32.051 ; 220.853,27.936 224.968,27.936 v5@224.968,32.051
28VGND1: C214_UB1.2 C221_UB1.2 C222_UB1.2 C223_UB1.2 C276_UB1.2 C277_UB1.1 DR2_UB1.2 P9_UB1.2 T2.1 T3_UB1.2 T4_UB1.4 | length 126.8
  Top Layer w2.54: v5@20.627,65.546 T4_UB1.4@20.627,73.33 ; C222_UB1.2@23.546,28.118 27.178,28.118 30.886,28.118 32.138,28.118 32.741,27.515 T2.1@32.741,21.057 ; v6@30.302,37.15 T3_UB1.2@35.789,37.15
  Mid-Layer 2 w2.54: v5@20.599,65.303 20.599,41.153 23.704,38.049 ; 23.561,38.192 23.704,38.049 ; P9_UB1.2@24.943,16.231 24.943,24.638 ; v6(29.693,37.135) 25.268,37.135 24.943,36.81 ; v6(32.156,24.536) 32.055,24.638 24.943,24.638 ; 23.704,38.049 v6(30.861,38.049) v6(30.861,36.119) 25.634,36.119 24.943,36.81 ; 23.704,38.049 24.943,36.81 ; 24.943,24.638 24.943,36.81 ; 24.943,24.638 25.73,25.425 v6(33.249,25.425) 33.249,23.647 25.933,23.647 24.943,24.638
  other v5: 20.472,65.303
  other v6: 33.147,23.52
28VGND2: C214_UB2.2 C221_UB2.2 C222_UB2.2 C223_UB2.2 C276_UB2.2 C277_UB2.1 DR2_UB2.2 P9_UB2.2 T3_UB2.2 T4_UB2.4 T5.1 | length 85.4
  Top Layer w2.54: T3_UB2.2@221.742,37.124 221.742,38.913 224.206,41.377 v5(234.62,41.377) 235.077,40.919 DR2_UB2.2@235.077,36.769 ; C222_UB2.2@228.727,27.788 238.862,27.788 v5@238.887,27.762 ; T5.1@231.318,21.184 231.318,19.253 234.163,16.408 P9_UB2.2@236.728,16.408 ; v5@238.049,67.107 v5(238.051,67.109) T4_UB2.4@238.051,75.626
  Bottom Layer w2.54: 230.988,41.402 231.445,41.402 231.47,41.377 v5(234.62,41.377) 239.344,41.377 241.325,43.358 241.325,66.269 240.485,67.109 v5(238.051,67.109)
  other v5: 239.09,27.559
28VGNDB_UB1: C269_UB1.1 C270_UB1.2 C271_UB1.2 C272_UB1.1 Q2_UB1.2 R264_UB1.2 T4_UB1.3 U47_UB1.4 UP6_UB1.1 | length 32.7
  Top Layer w2.54: T4_UB1.3@20.546,80.924 20.546,90.358 20.549,90.361 ; C270_UB1.2@20.549,88.976 20.549,91.135 23.063,91.135 26.619,94.691 UP6_UB1.1@28.885,94.691
  Bottom Layer w0.762: U47_UB1.4@27.717,100.609 28.423,100.609 28.423,96.825 28.296,96.698 ; C269_UB1.1@30.48,96.698 30.48,92.456 C272_UB1.1@30.531,92.405
  Bottom Layer w2.54: 26.619,94.691 UP6_UB1.1@28.885,94.691
28VGNDB_UB2: C269_UB2.1 C270_UB2.2 C271_UB2.2 C272_UB2.1 Q2_UB2.2 R264_UB2.2 T4_UB2.3 U47_UB2.4 UP6_UB2.1 | length 46.9
  Top Layer w0.762: v2(226.568,102.184) 226.568,97.694 227.158,97.104
  Top Layer w2.54: UP6_UB2.1@227.158,95.275 227.158,97.104 ; v5(236.195,98.476) 228.529,98.476 ; C270_UB2.2@237.851,86.055 C271_UB2.2@237.851,89.916 ; T4_UB2.3@237.896,82.756 v5@237.896,92.329 ; 227.158,97.104 227.158,98.826 227.101,98.882 228.123,98.882 228.529,98.476 ; 227.158,97.104 228.529,98.476
  Bottom Layer w0.762: U47_UB2.4@225.095,102.184 v2(226.568,102.184) 227,102.616 230.81,102.616 Q2_UB2.2@230.886,102.692
  Bottom Layer w2.54: v5(236.195,98.476) 237.922,98.476 v5@237.922,92.862
  other v5: 237.846,92.71
#CS_RAM_UB1: R316_UB1.2
#CS_RAM_UB2: R316_UB2.2
#CSZ0&Z1_UB1: R315_UB1.1 U55_UB1.145 | length 4.1
  Top Layer w0.254: U55_UB1.145@64.74,62.691 67.23,62.691 67.894,62.027 R315_UB1.1@68.553,62.027
#CSZ0&Z1_UB2: R315_UB2.1 U55_UB2.145 | length 2.8
  Top Layer w0.254: U55_UB2.145@221.585,62.996 223.618,62.996 R315_UB2.1@224.13,62.484
#CSZ0ANDZ1_UB1: R315_UB1.2
#CSZ0ANDZ1_UB2: R315_UB2.2
#CSZ6&Z7_UB1: R316_UB1.1 U55_UB1.150 | length 4.4
  Top Layer w0.254: U55_UB1.150@64.74,65.191 66.69,65.191 68.224,66.726 R316_UB1.1@68.478,66.726
#CSZ6&Z7_UB2: R316_UB2.1 U55_UB2.150 | length 3.1
  Top Layer w0.254: U55_UB2.150@221.585,65.496 222.798,65.496 224.053,66.751 R316_UB2.1@224.13,66.751
#PDPINTA_UB1: R336_UB1.2 R337_UB1.2 U55_UB1.24 | length 5.4
  Top Layer w0.254: U55_UB1.24@51.04,80.391 v1(51.04,83.642) 51.04,84.67 R337_UB1.2@51.054,84.684
  Mid-Layer 2 w0.254: v1(51.04,83.642) v1@51.054,83.656
  Bottom Layer w0.254: v1(51.04,83.642) 51.054,83.656 R336_UB1.2@51.054,84.684
#PDPINTA_UB2: R336_UB2.2 R337_UB2.2 U55_UB2.24 | length 9.9
  Top Layer w0.254: v1(206.299,83.972) 206.299,83.947 206.35,83.998 R337_UB2.2@206.35,84.836 ; 207.885,78.858 U55_UB2.24@207.885,80.696
  Bottom Layer w0.254: v1(206.299,83.972) 207.315,82.956 207.315,79.082 207.899,78.498 R336_UB2.2@207.899,77.521
  other v1: 207.975,78.511
#RD_UB1: R319_UB1.2
#RD_UB2: R319_UB2.2
#RESET_UB1: R346_UB1.1 R355_UB1.1 U55_UB1.80 | length 11.2
  Top Layer w0.254: v1@36.754,60.223 37.221,60.691 U55_UB1.80@38.84,60.691
  Top Layer w0.762: R346_UB1.1@34.722,67.386 34.798,67.31 R355_UB1.1@34.798,65.735
  Bottom Layer w0.254: v1(34.773,66.472) 34.773,65.837 36.932,63.678 36.932,60.401 v1@36.754,60.223
  other v1: 36.779,60.249
#RESET_UB2: R346_UB2.1 R355_UB2.1 U55_UB2.80 | length 38.6
  Top Layer w0.254: U55_UB2.80@195.685,60.996 v1@211.404,60.996 ; R355_UB2.1@226.797,72.613 226.822,72.588 v1(226.822,71.78) R346_UB2.1@226.822,71.095
  Bottom Layer w0.254: v1(211.404,60.884) 212.039,60.884 213.03,61.874 213.03,63.424 218.542,68.936 224.815,68.936 226.822,70.942 v1(226.822,71.78)
#TRST_UB1: C366_UB1.2 JP2_UB1.2 R302_UB1.2 U55_UB1.78 | length 14.7
  Top Layer w0.254: JP2_UB1.2@32.385,62.089 32.783,61.691 U55_UB1.78@38.84,61.691
  Bottom Layer w0.254: C366_UB1.2@27.076,57.76 R302_UB1.2@27.076,59.309 R302_UB1.2@27.178,59.411 ; R302_UB1.2@27.076,59.411 27.661,59.411 29.058,60.808 31.103,60.808 JP2_UB1.2@32.385,62.089
#TRST_UB2: C366_UB2.2 JP2_UB2.2 R302_UB2.2 U55_UB2.78 | length 42.5
  Top Layer w0.254: U55_UB2.78@195.685,61.996 214.726,61.996 215.392,62.662 v1(216.51,62.662)
  Bottom Layer w0.254: v1(216.51,62.662) 218.719,62.662 220.624,60.757 230.2,60.757 JP2_UB2.2@231.521,62.078 233.731,59.868 R302_UB2.2@234.016,59.868 234.016,58.293 C366_UB2.2@234.041,58.268
#WR_UB1: R317_UB1.2
#WR_UB2: R317_UB2.2
#XRD_UB1: R319_UB1.1 U55_UB1.149 | length 3.9
  Top Layer w0.254: U55_UB1.149@64.74,64.691 67.954,64.691 R319_UB1.1@68.465,65.202
#XRD_UB2: R319_UB2.1 U55_UB2.149 | length 2.7
  Top Layer w0.254: U55_UB2.149@221.585,64.996 223.797,64.996 R319_UB2.1@224.13,65.329
#XWE_UB1: R317_UB1.1 U55_UB1.137 | length 4.4
  Top Layer w0.254: U55_UB1.137@64.74,58.691 67.063,58.691 R317_UB1.1@68.553,57.201
#XWE_UB2: R317_UB2.1 U55_UB2.137 | length 2.9
  Top Layer w0.254: U55_UB2.137@221.585,58.996 223.376,58.996 R317_UB2.1@224.155,58.217
+1.9VD_UB1: C314_UB1.1 C321_UB1.1 C331_UB1.2 C332_UB1.2 C333_UB1.2 C334_UB1.2 C335_UB1.2 C336_UB1.2 C337_UB1.2 C338_UB1.2 C339_UB1.2 C340_UB1.2 C341_UB1.2 C342_UB1.2 C356_UB1.1 C357_UB1.1 C358_UB1.1 C359_UB1.1 LED11_UB1.1 R16_UB1.1 R295_UB1.2 U51_UB1.2 U55_UB1.4 U55_UB1.15 U55_UB1.23 U55_UB1.29 U55_UB1.61 U55_UB1.101 U55_UB1.109 U55_UB1.117 U55_UB1.126 U55_UB1.139 U55_UB1.146 U55_UB1.154 U55_UB1.167 | length 242.3
  Top Layer w0.254: U55_UB1.61@38.84,70.191 40.041,70.191 40.64,70.79 v2@40.64,70.967 ; U55_UB1.101@47.04,54.491 47.04,56.743 v1(47.269,56.972) ; U55_UB1.29@48.54,80.391 48.54,78.079 49.073,77.546 v1(49.073,77.241) ; v1(50.775,57.683) 51.04,57.418 U55_UB1.109@51.04,54.491 ; v1@51.54,78.515 U55_UB1.23@51.54,80.391 ; v1(54.712,56.691) 55.04,56.362 U55_UB1.117@55.04,54.491 ; v1(55.093,78.13) 55.54,78.578 U55_UB1.15@55.54,80.391 ; U55_UB1.126@59.54,54.491 59.54,56.238 v1(59.817,56.515) ; v1(60.731,78.41) 61.04,78.719 U55_UB1.4@61.04,80.391 ; v1(62.56,58.953) 62.636,58.953 63.374,59.691 U55_UB1.139@64.74,59.691 ; v1(62.611,73.838) 62.586,73.838 62.732,73.691 U55_UB1.167@64.74,73.691 ; v1(62.636,63.576) 62.789,63.576 63.174,63.191 U55_UB1.146@64.74,63.191 ; v1(62.662,66.675) 62.586,66.675 62.56,66.65 62.56,66.98 62.771,67.191 U55_UB1.154@64.74,67.191
  Top Layer w0.762: C331_UB1.2@50.267,42.266 v2(50.267,44.094) 50.292,44.12 C359_UB1.1@52.349,44.12
  Top Layer w1.27: R295_UB1.2@62.027,48.971 62.001,48.946 LED11_UB1.1@60.63,48.946 60.782,48.793 U51_UB1.2@60.782,46.584 60.782,44.78 61.468,44.094 v3(62.941,44.094) 65.227,44.094 ; C314_UB1.1@65.456,43.205 65.456,44.958 65.761,45.263 C321_UB1.1@66.192,45.263
  Mid-Layer 4 w0.762: v1(47.269,56.972) 47.269,54.635 47.32,54.585 ; 48.793,80.366 48.768,80.34 48.768,78.257 49.073,77.953 v1(49.073,77.241) ; 50.241,46.076 50.267,46.05 v2(50.267,44.094) ; v1(50.775,57.683) 50.978,57.48 50.978,54.585 ; v1@51.511,78.486 51.511,80.613 ; v1(54.712,56.691) 54.712,54.686 54.813,54.585 ; 54.915,80.613 55.093,80.436 v1(55.093,78.13) ; v1@59.792,56.515 59.792,54.788 59.995,54.585 ; 59.817,79.858 60.731,78.943 ; 60.579,80.613 60.731,80.461 60.731,78.943 ; v1(60.731,78.41) 60.731,78.943 ; v1(62.56,58.953) 64.833,58.953 64.96,58.826 ; v1(62.611,73.838) 63.195,73.838 ; v1(62.636,63.576) 64.833,63.576 64.96,63.449 ; v1(62.662,66.675) 64.808,66.675 64.96,66.523 ; 64.96,73.787 64.909,73.838 63.195,73.838 ; 64.973,72.923 64.11,72.923 63.195,73.838
  Mid-Layer 4 w1.016: 38.837,71.12 v2@40.462,71.12
  Mid-Layer 4 w2.54: 38.786,68.351 38.786,79.629 39.751,80.594 49.196,80.594 ; 38.862,70.358 38.862,56.007 38.938,55.931 ; 48.793,80.366 48.967,80.366 ; 49.215,80.613 54.915,80.613 ; 54.153,80.645 59.817,80.645 ; 64.96,66.523 64.96,63.449 64.96,58.826 64.96,56.146 63.398,54.585 54.813,54.585 40.284,54.585 38.938,55.931 ; 64.973,65.659 64.973,72.923 ; v7(38.938,53.238) 40.081,54.381 40.081,50.927 ; v7(38.938,53.238) 38.938,52.07 40.081,50.927 ; v7(38.938,53.238) 38.938,55.931 ; 40.081,50.927 40.081,48.87 42.875,46.076 50.241,46.076 59.563,46.076 ; 59.563,46.076 60.96,46.076 v3(62.941,44.094) 61.544,44.094 v3(61.036,44.602) 59.563,46.076
  Bottom Layer w0.762: C336_UB1.2@39.7,70.104 40.742,70.104 ; v2(40.665,71.12) 40.665,70.18 40.742,70.104 ; R16_UB1.1@41.173,70.104 40.742,70.104 ; C357_UB1.1@45.314,55.321 C338_UB1.2@47.346,55.321 47.346,56.896 v1(47.269,56.972) ; v1(49.073,77.241) 49.073,76.886 49.987,75.971 C339_UB1.2@52.273,75.971 ; v1(51.613,78.475) C340_UB1.2@51.613,79.553 ; v1(54.712,56.691) 54.737,56.666 C335_UB1.2@54.737,55.347 ; v1(55.093,78.13) C341_UB1.2@55.093,79.578 ; C332_UB1.2@59.792,55.321 59.792,56.49 v1(59.817,56.515) ; v1(60.731,78.41) C342_UB1.2@60.731,79.578 ; v1(62.56,58.953) 62.611,58.903 C337_UB1.2@64.059,58.903 ; v1(62.611,73.838) 62.84,73.609 C334_UB1.2@63.779,73.609 ; v1(62.636,63.576) 64.16,63.576 C356_UB1.1@64.211,63.627 ; v1(62.662,66.675) 63.906,66.675 C333_UB1.2@63.932,66.65
+1.9VD_UB2: C314_UB2.1 C321_UB2.1 C331_UB2.2 C332_UB2.2 C333_UB2.2 C334_UB2.2 C335_UB2.2 C336_UB2.2 C337_UB2.2 C338_UB2.2 C339_UB2.2 C340_UB2.2 C341_UB2.2 C342_UB2.2 C356_UB2.1 C357_UB2.1 C358_UB2.1 C359_UB2.1 LED11_UB2.1 R16_UB2.1 R295_UB2.2 U51_UB2.2 U55_UB2.4 U55_UB2.15 U55_UB2.23 U55_UB2.29 U55_UB2.61 U55_UB2.101 U55_UB2.109 U55_UB2.117 U55_UB2.126 U55_UB2.139 U55_UB2.146 U55_UB2.154 U55_UB2.167 | length 198.5
  Top Layer w0.254: U55_UB2.61@195.685,70.496 197.017,70.496 v2@197.485,70.028 ; U55_UB2.101@203.885,54.796 v1(203.886,56.566) ; U55_UB2.29@205.385,80.696 205.385,79.374 205.715,79.045 v1@206.299,79.045 ; v1(207.493,57.074) 207.885,56.681 U55_UB2.109@207.885,54.796 ; U55_UB2.23@208.385,80.696 208.385,79.27 208.712,78.943 208.712,78.105 209.093,77.724 v1@209.55,77.724 ; v1(211.43,56.667) 211.6,56.667 211.885,56.382 U55_UB2.117@211.885,54.796 ; v1(212.141,78.74) 212.385,78.984 U55_UB2.15@212.385,80.696 ; U55_UB2.126@216.385,54.796 216.385,56.543 v1(216.56,56.718) ; v1(217.856,78.74) 217.885,78.711 U55_UB2.4@217.885,80.696 ; v1@218.516,60.554 218.516,60.147 218.973,59.69 219.71,59.69 220.016,59.996 U55_UB2.139@221.585,59.996 ; v1(219.71,63.5) 219.714,63.496 U55_UB2.146@221.585,63.496 ; v1(219.71,67.285) 219.921,67.496 U55_UB2.154@221.585,67.496 ; v1(219.71,74.244) 219.958,73.996 U55_UB2.167@221.585,73.996
  Top Layer w1.27: U51_UB2.2@207.442,46.025 207.442,44.247 207.696,43.993 v3(207.975,43.993) 213.335,43.993 ; R295_UB2.2@213.335,46.304 213.335,43.993 ; 214.554,42.71 214.554,43.777 214.325,44.005 214.287,44.005 214.274,43.993 213.335,43.993
  Mid-Layer 2 w0.508: 208.788,79.578 208.788,78.029 209.042,77.775 v1(209.6,77.775) 209.6,77.217 210.083,76.733 ; 211.303,80.696 212.141,79.858 v1(212.141,78.74) 212.141,77.749 ; 217.043,77.394 217.856,78.207 v1(217.856,78.74) 217.856,80.67 217.881,80.696 ; 217.602,60.681 217.653,60.63 v1(218.516,60.63) 218.516,59.538 218.389,59.411 ; 218.745,74.244 v1(219.71,74.244) 221.869,74.244 ; 219.735,62.738 219.71,62.763 v1(219.71,63.5) 221.818,63.5 221.869,63.449
  Mid-Layer 2 w0.762: 195.707,69.571 196.19,70.053 v2(197.536,70.053)
  Mid-Layer 2 w2.032: 195.707,69.571 195.707,57.605 198.525,54.788 209.245,54.788 ; 206.299,79.756 206.299,80.67 206.273,80.696 211.303,80.696
  Mid-Layer 2 w2.54: v3(207.975,43.993) 211.226,43.993 213.233,45.999 218.008,45.999 221.869,49.86 221.869,54.788 ; 209.245,54.788 221.869,54.788 ; 211.303,80.696 217.881,80.696 220.066,80.696 221.869,78.892 221.869,74.244 221.869,63.449 221.869,54.788
  Bottom Layer w0.508: v1(206.172,79.019) 206.375,79.223 C335_UB2.2@206.375,80.086 ; C332_UB2.2@211.785,80.162 212.242,80.162 ; v1(212.141,78.74) 212.141,80.061 212.242,80.162 ; C356_UB2.1@213.817,80.213 213.766,80.162 212.242,80.162 ; C331_UB2.2@217.78,79.832 217.78,78.816 v1(217.856,78.74) ; v1(219.71,63.5) C341_UB2.2@220.751,63.5 220.751,66.827 C357_UB2.1@221.158,67.234 219.761,67.234 v1(219.71,67.285) ; v1(219.71,74.244) 219.786,74.32 220.955,74.32 220.955,74.295 C342_UB2.2@221.056,74.193
  Bottom Layer w0.762: C336_UB2.2@195.326,75.54 C359_UB2.1@195.326,73.613 195.326,72.644 195.758,72.212 195.809,72.212 196.088,71.933 196.088,71.349 C334_UB2.2@196.393,71.044 197.383,70.053 v2(197.536,70.053) 198.298,69.291 R16_UB2.1@198.831,69.291 ; v1(203.886,56.566) 203.86,56.54 203.86,55.575 ; v1(207.493,57.074) 207.493,55.601 C338_UB2.2@207.239,55.347 207.061,55.169 C358_UB2.1@205.257,55.169 ; v1(211.43,56.667) 211.531,56.566 C339_UB2.2@211.531,55.55 ; C340_UB2.2@216.56,55.677 v1(216.56,56.718) ; 203.86,55.575 203.378,55.575 203.784,55.169 C358_UB2.1@205.257,55.169 ; 203.86,55.575 204.851,55.575 C358_UB2.1@205.257,55.169
  other v3: 209.677,43.967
